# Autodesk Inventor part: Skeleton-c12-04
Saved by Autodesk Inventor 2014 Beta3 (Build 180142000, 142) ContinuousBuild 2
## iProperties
Created: 2011-01
Part Number: Skeleton-c12-04
Material: Generic
Document SubType Name: Modeling
Designer: Thom Tremblay
Density: 1 g/cm^3
Appearance: Generic
_SkeletonDoc: Frame Skeleton File
_Version: 15.0.0
Author: Thom Tremblay
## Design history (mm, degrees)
sketch "Reference Skeleton"
  geometry: L1 through (404.523, 1164.395) direction (1, 0); L2 through (325.691, 1070.446) direction (1, 0); 34 other entities
  constraints: 10 horizontal
